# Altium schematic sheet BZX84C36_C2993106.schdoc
size 127 x 101 mm
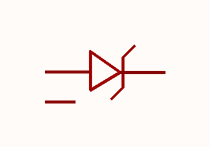
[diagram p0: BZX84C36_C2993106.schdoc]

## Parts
D?  bzx84c36_c2993106  [SOT-23-3_L2.9-W1.3-P1.90-LS2.4-BR]  (value not drawn)

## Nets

Not connected (* = marked no-connect by the designer): D? 1(A) 2 3(C)

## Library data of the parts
D? = bzx84c36_c2993106: 二极管配置:1个独立式;稳压值(标称值):36V;稳压值(范围):36V~38V;耗散功率(Pd):300mW;; Manufacturer: MDD(辰达半导体); AddInBom: yes; ModelId: c62791f0466c4ae2a892c056b845b0ca; ModelName: SOT-23-3P_L2.9-W1.3-H1.0-LS2.4-P0.95; ModelTransform: 98.425,114.173,0,180,0,0,0.0005,-0.0005,0; Diode Configuration: 1个独立式; Zener Voltage(Nom): 36V; Reverse Leakage Current (Ir): 100nA@25.2V; Pd - Power Dissipation: 300mW; Impedance(Zzt): 90Ω; Impedance(Zzk): 350Ω; Operating Junction Temperature Range: -55℃~+150℃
